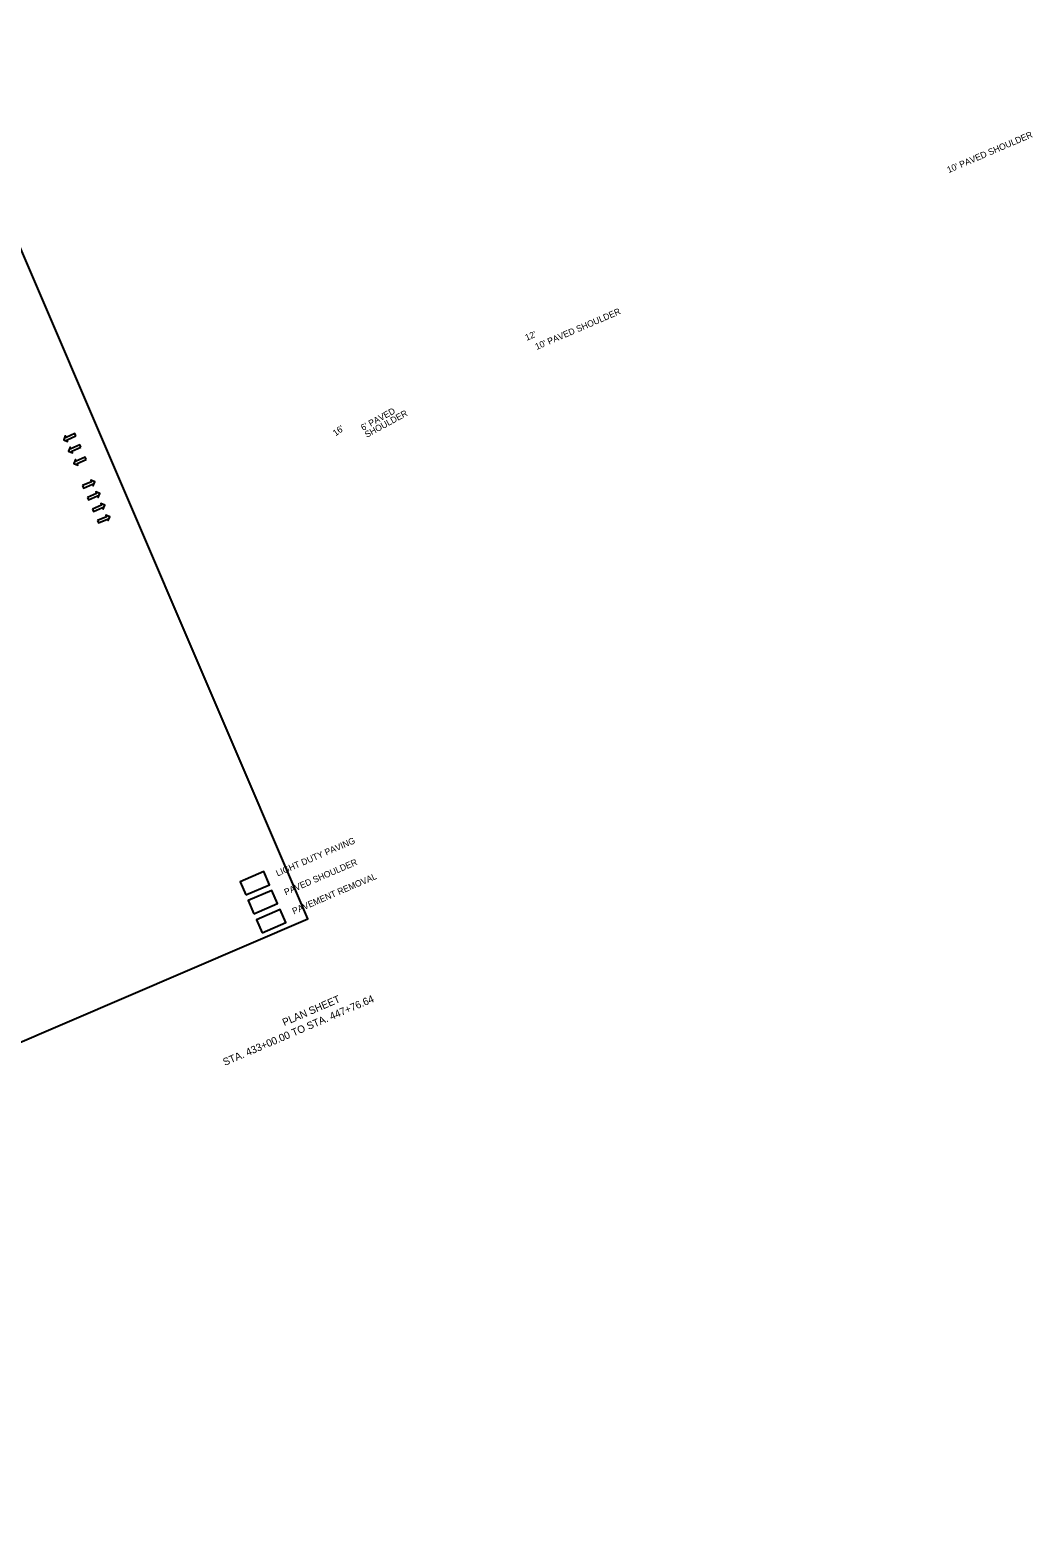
# Model space of a CAD drawing. Extents: x 1621035 to 1623496, y 1102384 to 1103996.
# Drawn here: x 1622552 to 1623496, y 1102384 to 1103803 of the extents above; entities that cross this region are included whole.
import ezdxf

# ---------------------------------------------------------------- set-up
doc = ezdxf.new("R2010")
doc.units = 0
for name, color, linetype in [('RD_EX_GuardRail', 7, 'Continuous'), ('RD_EX_RW', 7, 'Continuous'), ('RD_HC_Data_Tic_Rel', 7, 'Continuous'), ('RD_PD_Final_TX', 7, 'Continuous')]:
    doc.layers.add(name, color=color, linetype=linetype)

msp = doc.modelspace()

# ---------------------------------------------------------------- linework, layer by layer
at = {"layer": 'RD_EX_GuardRail'}
for points in [[(1622595.2, 1103421.3), (1622594.3, 1103423.5), (1622585.9, 1103419.9), (1622585.2, 1103421.4), (1622583.7, 1103417.7), (1622587.4, 1103416.2), (1622586.8, 1103417.7)], [(1622599.8, 1103410.6), (1622598.9, 1103412.8), (1622590.5, 1103409.1), (1622589.8, 1103410.6), (1622588.3, 1103406.9), (1622592.1, 1103405.4), (1622591.4, 1103406.9)], [(1622604.8, 1103399), (1622603.9, 1103401.2), (1622595.4, 1103397.6), (1622594.8, 1103399.1), (1622593.3, 1103395.3), (1622597, 1103393.9), (1622596.4, 1103395.4)], [(1622601.4, 1103374.5), (1622602.3, 1103372.3), (1622610.8, 1103375.9), (1622611.4, 1103374.4), (1622612.9, 1103378.1), (1622609.2, 1103379.6), (1622609.8, 1103378.1)], [(1622606.1, 1103363.5), (1622607.1, 1103361.3), (1622615.5, 1103364.9), (1622616.1, 1103363.4), (1622617.6, 1103367.1), (1622613.9, 1103368.6), (1622614.5, 1103367.1)], [(1622610.8, 1103352.4), (1622611.8, 1103350.2), (1622620.2, 1103353.8), (1622620.9, 1103352.4), (1622622.3, 1103356.1), (1622618.6, 1103357.6), (1622619.3, 1103356.1)], [(1622615.5, 1103341.7), (1622616.4, 1103339.5), (1622624.8, 1103343.1), (1622625.5, 1103341.6), (1622627, 1103345.3), (1622623.3, 1103346.8), (1622623.9, 1103345.3)]]:
    msp.add_lwpolyline(points, close=True, dxfattribs=at)
at = {"layer": 'RD_EX_RW'}
for points in [[(1622755.1, 1102989.4), (1622777.4, 1102998.9), (1622772.1, 1103011.3), (1622749.8, 1103001.7)], [(1622762.8, 1102971.5), (1622785.1, 1102981.1), (1622779.8, 1102993.4), (1622757.5, 1102983.9)], [(1622770.5, 1102953.6), (1622792.8, 1102963.2), (1622787.5, 1102975.6), (1622765.2, 1102966)]]:
    msp.add_lwpolyline(points, close=True, dxfattribs=at)
for points in [[(1622755.1, 1102989.4), (1622777.4, 1102998.9), (1622772.1, 1103011.3), (1622749.8, 1103001.7), (1622755.1, 1102989.4)], [(1622762.8, 1102971.5), (1622785.1, 1102981.1), (1622779.8, 1102993.4), (1622757.5, 1102983.9), (1622762.8, 1102971.5)], [(1622770.5, 1102953.6), (1622792.8, 1102963.2), (1622787.5, 1102975.6), (1622765.2, 1102966), (1622770.5, 1102953.6)]]:
    msp.add_lwpolyline(points, dxfattribs=at)
at = {"layer": 'RD_PD_Final_TX'}
msp.add_lwpolyline([(1621300.1, 1102746.8), (1621324, 1102752.9), (1621344.3, 1102622.5), (1621455.7, 1102384.2), (1622813.6, 1102966.9), (1622454.7, 1103803.2), (1622329.1, 1103749.7), (1622315, 1103780.9), (1621083.2, 1103252.2)], close=True, dxfattribs=at)
msp.add_lwpolyline([(1621300.1, 1102746.8), (1621324, 1102752.9), (1621344.3, 1102622.5), (1621455.7, 1102384.2), (1622813.6, 1102966.9), (1622454.7, 1103803.2), (1622329.1, 1103749.7), (1622315, 1103780.9), (1621083.2, 1103252.2)], close=True, dxfattribs=at)

# ---------------------------------------------------------------- texts
at = {"layer": 'RD_EX_RW'}
for s, rotation, p in [("10' PAVED SHOULDER", 23.2267, (1623417, 1103668.6)), ("10' PAVED SHOULDER", 23.2267, (1623029.1, 1103502.2)), ("12'", 23.2346, (1623019.7, 1103510.8)), ("6' PAVED", 28.7789, (1622865.5, 1103426)), ('SHOULDER', 28.7789, (1622869.1, 1103419.4)), ("16'", 36.6989, (1622839.8, 1103420.8)), ('LIGHT DUTY PAVING', 23.2284, (1622785.1, 1103006.6)), ('PAVED SHOULDER', 23.2284, (1622792.8, 1102988.8)), ('PAVEMENT REMOVAL', 23.2284, (1622800.4, 1102970.9))]:
    msp.add_text(s, height=6, rotation=rotation, dxfattribs=at).set_placement(p)
at = {"layer": 'RD_HC_Data_Tic_Rel'}
for s, height, p in [('STA. 433+00.00 TO STA. 447+76.64', 6.983, (1622735.4, 1102828.3)), ('PLAN SHEET', 6.98, (1622791.4, 1102865.8))]:
    msp.add_text(s, height=height, rotation=23.2284, dxfattribs=at).set_placement(p)

doc.saveas('drawing.dxf')
